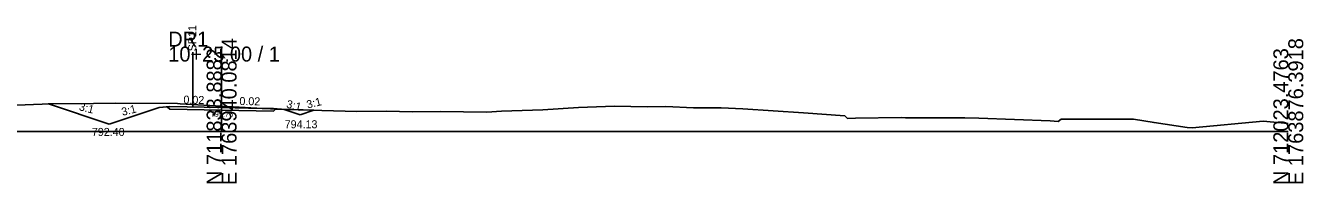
# Model space of a CAD drawing. Extents: x -26 to 403, y -10 to 2023.
# Drawn here: x 163.2 to 402.8, y 490.3 to 519.8 of the extents above; entities that cross this region are included whole.
import ezdxf

# ---------------------------------------------------------------- set-up
doc = ezdxf.new("R2010")
doc.units = 0
for name, color, linetype in [('Exist Cross Section Cell', 7, 'Continuous'), ('Exist XS Center Line Elevation Label', 7, 'Continuous'), ('Exist XS Ground Line', 7, 'Continuous'), ('Prop CMT Pvmt Surface', 7, 'Continuous'), ('Prop CMT Slope Grass', 7, 'Continuous'), ('Prop CMT Subgrade Earthwork', 7, 'Continuous'), ('Prop XS Earthwork Shape', 7, 'Continuous'), ('Prop XS Shear Point Element', 7, 'Continuous'), ('Prop XS Side Slope Text', 7, 'Continuous')]:
    doc.layers.add(name, color=color, linetype=linetype)

msp = doc.modelspace()

# ---------------------------------------------------------------- linework, layer by layer
at = {"layer": 'Exist Cross Section Cell'}
for p, q in [((200, 500), (200, 515.9)), ((0, 500), (200, 500)), ((200, 500), (400, 500))]:
    msp.add_line(p, q, dxfattribs=at)
at = {"layer": 'Exist XS Ground Line'}
msp.add_lwpolyline([(153.56, 504.63), (167.94, 505.22), (176.01, 505.25), (180.02, 505.3), (191.72, 505.26), (192.22, 505.22), (200, 504.76), (206.59, 504.38), (208.24, 504.3), (210.07, 504.2), (225.38, 503.74), (230.85, 503.81), (235.84, 503.69), (241, 503.73), (249.71, 503.65), (252.51, 503.8), (260.22, 504.06), (266.9, 504.48), (273.65, 504.74), (279.79, 504.65), (283.32, 504.72), (288.48, 504.45), (293.66, 504.45), (297.7, 504.27), (309.1, 503.52), (316.84, 502.96), (317.34, 502.45), (318.85, 502.51), (327.39, 502.61), (328.23, 502.6), (328.99, 502.58), (330.69, 502.55), (331.33, 502.6), (338.4, 502.6), (338.91, 502.58), (339.38, 502.57), (341.98, 502.51), (355.33, 501.99), (356.88, 501.86), (357.4, 502.34), (357.95, 502.33), (370.95, 502.35), (374.85, 501.69), (381.04, 500.78), (381.97, 500.7), (395.27, 501.94), (400, 501.54)], dxfattribs=at)
at = {"layer": 'Prop CMT Pvmt Surface'}
for q in [(190.29, 504.68), (209.72, 504.29)]:
    msp.add_line((200, 504.48), q, dxfattribs=at)
at = {"layer": 'Prop CMT Slope Grass'}
for p, q in [((178.94, 501.4), (167.53, 505.2)), ((188.29, 504.52), (178.94, 501.4)), ((211.72, 504.13), (214.72, 503.13)), ((214.72, 503.13), (217.28, 503.98))]:
    msp.add_line(p, q, dxfattribs=at)
for points in [[(190.29, 504.68), (188.29, 504.52)], [(209.72, 504.29), (211.72, 504.13)]]:
    msp.add_lwpolyline(points, dxfattribs=at)
at = {"layer": 'Prop CMT Subgrade Earthwork'}
for p, q in [((190.28, 504.18), (189.82, 504.64)), ((199.99, 503.98), (190.28, 504.18)), ((199.99, 503.98), (209.71, 503.79)), ((209.71, 503.79), (210.17, 504.25))]:
    msp.add_line(p, q, dxfattribs=at)
at = {"layer": 'Prop XS Earthwork Shape'}
for points in [[(178.94, 501.4), (167.53, 505.2), (167.94, 505.22), (176.01, 505.25), (180.02, 505.3), (191.72, 505.26), (192.22, 505.22), (200, 504.76), (206.59, 504.38), (207.63, 504.33), (200, 504.48), (190.29, 504.68), (189.82, 504.64), (188.29, 504.52)], [(200, 504.48), (207.63, 504.33), (208.24, 504.3), (210.07, 504.2), (210.12, 504.2), (209.71, 503.79), (199.99, 503.98), (190.28, 504.18), (189.82, 504.64), (190.29, 504.68)], [(210.17, 504.25), (211.25, 504.17), (210.12, 504.2)], [(214.72, 503.13), (217.28, 503.98), (211.25, 504.17), (211.72, 504.13)]]:
    msp.add_lwpolyline(points, close=True, dxfattribs=at)
at = {"layer": 'Prop XS Shear Point Element'}
msp.add_line((194.63, 504.59), (194.63, 514.88), dxfattribs=at)

# ---------------------------------------------------------------- texts
at = {"layer": 'Exist Cross Section Cell'}
for s, p in [('DR1', (190, 515.9)), ('10+25.00 / 1', (190, 513.1))]:
    msp.add_text(s, height=2.8, dxfattribs=at).set_placement(p)
for s, p in [('N 711833.8882', (200, 490)), ('E 1763940.0814', (202.8, 490)), ('N 712023.4763', (400, 490)), ('E 1763876.3918', (402.8, 490))]:
    msp.add_text(s, height=2.8, rotation=90, dxfattribs=at).set_placement(p)
at = {"layer": 'Exist XS Center Line Elevation Label'}
for s, height, p in [('795.76', 1, (197.94, 502.76)), ('794.13', 1.5, (211.83, 500.62)), ('792.40', 1.5, (175.68, 499.18))]:
    msp.add_text(s, height=height, dxfattribs=at).set_placement(p)
at = {"layer": 'Prop XS Shear Point Element'}
msp.add_text('SP11', height=1.5, rotation=90, dxfattribs=at).set_placement((195.25, 515.02))
at = {"layer": 'Prop XS Side Slope Text'}
for s, rotation, p in [('0.02', 358.8542, (192.83, 505.23)), ('0.02', 358.8542, (203.33, 504.97)), ('3:1', 345.9638, (212.04, 504.51)), ('3:1', 14.0362, (216.14, 504.29)), ('3:1', 345.9638, (173.16, 504.02)), ('3:1', 14.0362, (181.43, 502.93))]:
    msp.add_text(s, height=1.5, rotation=rotation, dxfattribs=at).set_placement(p)

doc.saveas('drawing.dxf')
